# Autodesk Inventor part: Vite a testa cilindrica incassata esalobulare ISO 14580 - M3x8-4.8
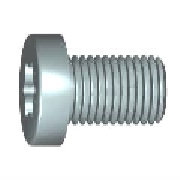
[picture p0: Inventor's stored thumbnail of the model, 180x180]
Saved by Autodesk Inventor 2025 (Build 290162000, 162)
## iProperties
Created: 2024-01
Part Number: Vite a testa cilindrica incassata esalobulare ISO 14580 - M3x8-4.8
Material: Acciaio
Description: ISO 14580 - Viti a testa cilindrica incassata esalobulare - Seconda edizione
Document SubType Name: Modeling
Standard: 14580
Designer: Ryzen5700u
Standards Organization: ISO
Language: it-IT
Size Designation: M3x8-4.8
Categories: <MemberInstance><Categories><Category DisplayName="Elementi di fissaggio" InternalName="e4da775c-781d-43d5-af7c-5136215cf5a6" Mnemonic="FSTN"><Category DisplayN
Density: 7.85 g/cm^3
Appearance: Lamiera
IsCustomPart: 0
Author: Ryzen5700u
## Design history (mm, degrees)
revolve "Revolution1" stored, may be unused: angle "d4" = 90 deg
thread "Thread1" dims "d6" = 8 (= b), "d7" = 0
sketch "Sketch2" dims "d21" = 2.8 (= A_)
  geometry: L1 (-0.849, -0.49)-(-1.4, 0); L2 (0, 0)-(-0.849, -0.49); L3 (0, 0)-(-0.849, 0.49); L4 (-4.144, 0)-(4.144, 0) reference; L5 (-1.4, 0)-(-0.849, 0.49); A1 r 0.98 centre (0, 0) between (-0.849, -0.49) and (-0.849, 0.49); 2 further points
  constraints: 8 end point, 2 coincident, 2 point on circle, 1 centre point, 1 horizontal alignment, 1 point on line, 2 other
  dimensions: "d19" = 60 deg angle of L3 L2; "d20" = 30 deg angle of L3 L4 (= 0.5 x d19); "d26" = 1.96 diameter of A1 (= 0.7 x d21)
extrude "Extrusion1" cut sketch "Sketch2" distance "d27" = 1.27 (= t); taper "d28" = 0 deg
pattern_circular "Circular Pattern1" dims angle "d30" = 360 deg
fillet "Fillet2" dims "d32" = 0.3 (= v)
fillet "Fillet3" dims "d33" = 0.3 (= v)
fillet "Fillet5" dims "d35" = 0.1 (= r)
chamfer "Chamfer2" distance "d36" = 0.3 (= v); stored, may be unused: second distance "d37" = 2, angle "d38" = 45 deg
body "Solid1"
sketch "Sketch1"
  geometry: L1 (0, 0)-(8, 0); L2 (8, 0)-(8, 1.5); L3 (8, 1.5)-(0, 1.5); L4 (0, 1.5)-(0, 0); L5 (0, 0)-(-2.4, 0); L6 (-2.4, 0)-(-2.4, 2.75); L7 (-2.4, 2.75)-(0, 2.96); L8 (0, 2.96)-(0, 0)
  constraints: 16 end point, 3 parallel, 2 horizontal, 2 perpendicular
  dimensions: "d0" = 3 diameter of L3 L1 (= d); "d3" = 8 distance of L2.end L3.end (= l_); "d46" = 85 deg angle of L8 L7; "d47" = 2.4 distance between parallel lines of L8 L6 (= k); "d49" = 5.5 diameter of L6.end L1 (= dk)
other parameters: "A_" = 2.8 [user parameter; used in 1 equation term], "d" = 3 [user parameter; used in 2 equation terms], "dk" = 5.5 [user parameter; used in 1 equation term], "k" = 2.4 [user parameter; used in 1 equation term], "l_" = 8 [user parameter; used in 2 equation terms], "lg" = 0 [user parameter; used in 1 equation term], "t" = 1.27 [user parameter; used in 1 equation term], "w" = 0.55 [user parameter], "v" = 0.3 [user parameter; used in 3 equation terms], "r" = 0.1 [user parameter; used in 1 equation term], "da" = 2.6 [user parameter], "ds_" = 3 (= d) [user parameter], "ls" = 0 [user parameter], "b" = 8 (= l_ - lg) [user parameter; used in 1 equation term], "d42" = 0, "d43" = 0, "d44" = 0, "p" = 0.5 [user parameter]
